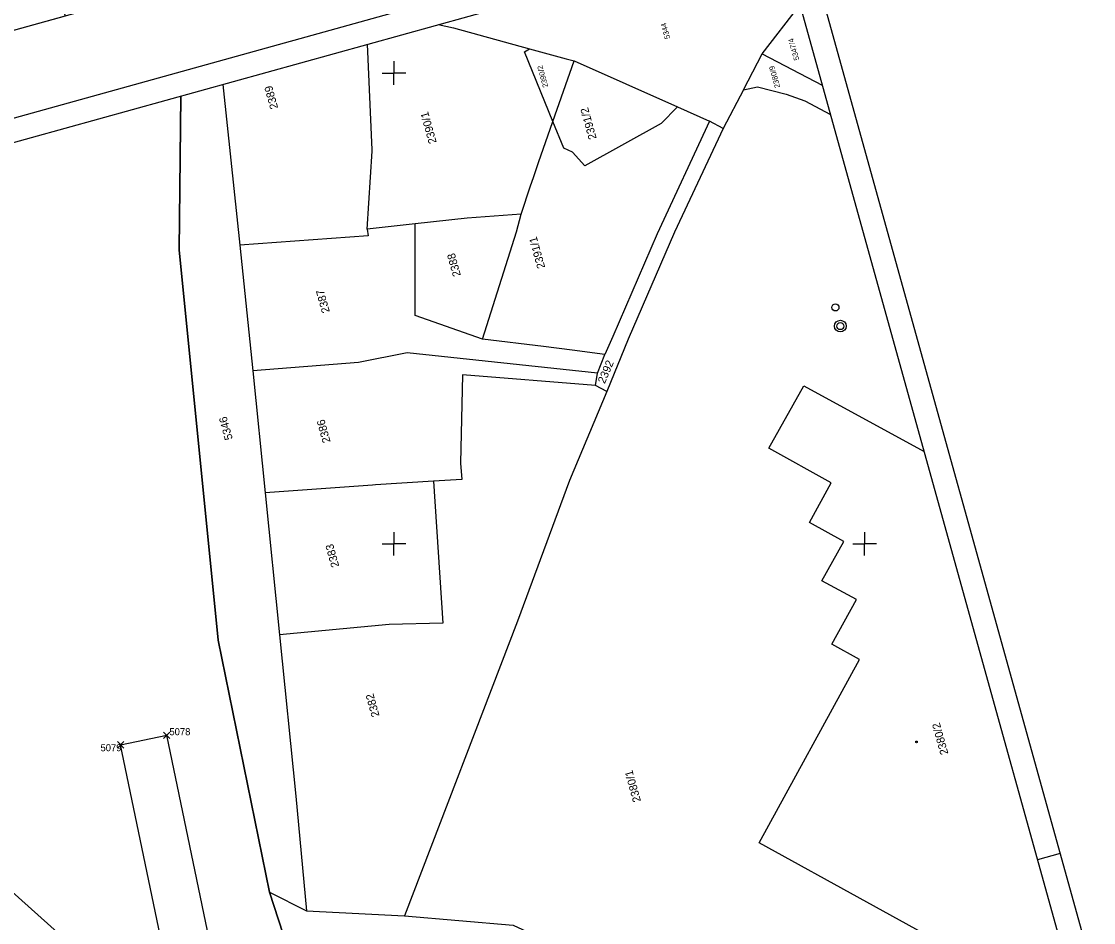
# Model space of a CAD drawing. Extents: x -821172 to -820632, y -1070921 to -1069931.
# Drawn here: x -820939.6 to -820825.7, y -1070140.2 to -1070044.5 of the extents above; entities that cross this region are included whole.
import ezdxf

# ---------------------------------------------------------------- set-up
doc = ezdxf.new("R2010")
doc.units = 0
for name, color, linetype in [('Popisove_pole', 7, 'Continuous'), ('Ram', 7, 'Continuous'), ('Sit', 7, 'Continuous'), ('VB_bod_DZ', 7, 'Continuous'), ('Vrstva 52', 7, 'Continuous'), ('Vrstva 53', 7, 'Continuous'), ('Vrstva 55', 7, 'Continuous'), ('Vrstva 57', 7, 'Continuous'), ('Vrstva 59', 7, 'Continuous'), ('Vrstva 7', 7, 'Continuous')]:
    doc.layers.add(name, color=color, linetype=linetype)

msp = doc.modelspace()

# ---------------------------------------------------------------- linework, layer by layer
at = {"layer": 'Popisove_pole'}
for points in [[(-820992.73, -1070060.01), (-821015.48, -1069978.12), (-820890.23, -1069943.31), (-820867.47, -1070025.21)], [(-820946.96, -1070047.3), (-820969.72, -1069965.4), (-820957.67, -1069962.05), (-820934.92, -1070043.95)]]:
    msp.add_lwpolyline(points, close=True, dxfattribs=at)
at = {"layer": 'Ram'}
for p, q in [((-820859.09, -1070034.8), (-821140.43, -1070112.97)), ((-820829.24, -1070132.89), (-820831.65, -1070133.56))]:
    msp.add_line(p, q, dxfattribs=at)
for points in [[(-820857.35, -1070031.72), (-821000.43, -1070071.48)], [(-820857.35, -1070031.72), (-820632.46, -1070841.06)], [(-820859.09, -1070034.8), (-820635.54, -1070839.32), (-820916.88, -1070917.49)]]:
    msp.add_lwpolyline(points, dxfattribs=at)
at = {"layer": 'Sit'}
for p, q in [((-820900, -1070048.75), (-820900, -1070050)), ((-820901.25, -1070050), (-820900, -1070050)), ((-820898.75, -1070050), (-820900, -1070050)), ((-820900, -1070051.25), (-820900, -1070050)), ((-820900, -1070098.75), (-820900, -1070100)), ((-820850, -1070098.75), (-820850, -1070100)), ((-820901.25, -1070100), (-820900, -1070100)), ((-820898.75, -1070100), (-820900, -1070100)), ((-820900, -1070101.25), (-820900, -1070100)), ((-820851.25, -1070100), (-820850, -1070100)), ((-820848.75, -1070100), (-820850, -1070100)), ((-820850, -1070101.25), (-820850, -1070100))]:
    msp.add_line(p, q, dxfattribs=at)
at = {"layer": 'VB_bod_DZ'}
for p, q in [((-820924.48, -1070120.68), (-820923.79, -1070119.99)), ((-820923.79, -1070120.68), (-820924.48, -1070119.99)), ((-820929.37, -1070121.7), (-820928.68, -1070121.01)), ((-820928.68, -1070121.7), (-820929.37, -1070121.01))]:
    msp.add_line(p, q, dxfattribs=at)
at = {"layer": 'Vrstva 52'}
msp.add_line((-820929.03, -1070121.35), (-820924.13, -1070120.33), dxfattribs=at)
for points in [[(-820888.38, -1070203.11), (-820893.8, -1070195), (-820900.76, -1070183.17), (-820906.67, -1070169.8), (-820914.74, -1070165.47), (-820924.13, -1070120.33)], [(-820905.06, -1070185.73), (-820910.61, -1070187.13), (-820917.29, -1070174.93), (-820923.8, -1070161.07), (-820931.72, -1070145.81), (-820933.72, -1070143.08), (-820957.69, -1070121.63)], [(-820905.06, -1070185.73), (-820905.22, -1070185.45), (-820910.55, -1070173.4), (-820919.16, -1070168.77), (-820929.03, -1070121.35)]]:
    msp.add_lwpolyline(points, dxfattribs=at)
at = {"layer": 'Vrstva 53'}
for points in [[(-820922.62, -1070052.45), (-820922.83, -1070068.79), (-820918.68, -1070110.25), (-820913.23, -1070137.01)], [(-820913.23, -1070137.01), (-820910.8, -1070144.4), (-820907.37, -1070147.11)]]:
    msp.add_lwpolyline(points, dxfattribs=at)
at = {"layer": 'Vrstva 55'}
for p, q in [((-820860.9, -1070047.95), (-820856.87, -1070042.78)), ((-820862.88, -1070051.77), (-820860.9, -1070047.95)), ((-820860.9, -1070047.95), (-820854.51, -1070051.28)), ((-820883.11, -1070055.15), (-820880.86, -1070048.72)), ((-820880.86, -1070048.72), (-820869.88, -1070053.59)), ((-820862.88, -1070051.77), (-820865.03, -1070055.9)), ((-820869.88, -1070053.59), (-820866.48, -1070055.1)), ((-820865.03, -1070055.9), (-820866.48, -1070055.1)), ((-820897.74, -1070066.03), (-820902.85, -1070066.6)), ((-820916.36, -1070068.27), (-820914.97, -1070081.64)), ((-820878.36, -1070081.89), (-820877.58, -1070079.88)), ((-820914.97, -1070081.64), (-820913.68, -1070094.59)), ((-820878.59, -1070083.2), (-820878.36, -1070081.89)), ((-820877.39, -1070083.81), (-820878.59, -1070083.2)), ((-820913.68, -1070094.59), (-820912.16, -1070109.68)), ((-820913.23, -1070137.01), (-820909.27, -1070138.99)), ((-820909.27, -1070138.99), (-820898.88, -1070139.5))]:
    msp.add_line(p, q, dxfattribs=at)
for points in [[(-820895.31, -1070044.86), (-820893.67, -1070045.22), (-820885.61, -1070047.42)], [(-820902.85, -1070066.6), (-820902.3, -1070058.3), (-820902.3, -1070058.17), (-820902.8, -1070046.94)], [(-820883.11, -1070055.15), (-820886.13, -1070047.76), (-820885.61, -1070047.42)], [(-820885.61, -1070047.42), (-820881.69, -1070048.49), (-820880.86, -1070048.72)], [(-820918.18, -1070051.22), (-820917.32, -1070059.26), (-820916.36, -1070068.27)], [(-820913.23, -1070137.01), (-820918.68, -1070110.25), (-820922.83, -1070068.79), (-820922.62, -1070052.43)], [(-820862.88, -1070051.77), (-820861.37, -1070051.48), (-820858.35, -1070052.26), (-820856.35, -1070052.96), (-820853.61, -1070054.39)], [(-820869.88, -1070053.59), (-820871.63, -1070055.37), (-820879.71, -1070059.86), (-820881.02, -1070058.42), (-820881.94, -1070057.97), (-820883.11, -1070055.15)], [(-820886.5, -1070064.99), (-820885.48, -1070061.97), (-820885.19, -1070061.1), (-820884.63, -1070059.51), (-820883.11, -1070055.15)], [(-820866.48, -1070055.1), (-820872.03, -1070067.08), (-820876.75, -1070077.98), (-820877.58, -1070079.88)], [(-820865.03, -1070055.9), (-820870.19, -1070066.92), (-820875.13, -1070078.28), (-820877.39, -1070083.81)], [(-820886.5, -1070064.99), (-820892.22, -1070065.41), (-820897.74, -1070066.03)], [(-820890.6, -1070078.28), (-820886.98, -1070066.87), (-820886.5, -1070064.99)], [(-820890.6, -1070078.28), (-820897.74, -1070075.76), (-820897.74, -1070066.03)], [(-820902.85, -1070066.6), (-820902.73, -1070067.28), (-820916.36, -1070068.27)], [(-820877.58, -1070079.88), (-820881.08, -1070079.43), (-820884.11, -1070079.05), (-820890.6, -1070078.28)], [(-820878.36, -1070081.89), (-820898.58, -1070079.72), (-820903.75, -1070080.75), (-820914.97, -1070081.64)], [(-820878.59, -1070083.2), (-820892.71, -1070082.07), (-820892.93, -1070091.44), (-820892.8, -1070093.17), (-820895.78, -1070093.35)], [(-820826.9, -1070150.65), (-820861.21, -1070131.75), (-820850.55, -1070112.3), (-820853.49, -1070110.66), (-820850.87, -1070105.91), (-820854.53, -1070103.94), (-820852.21, -1070099.75), (-820855.86, -1070097.75), (-820853.56, -1070093.52), (-820860.16, -1070089.86), (-820856.47, -1070083.21), (-820843.69, -1070090.21)], [(-820877.39, -1070083.81), (-820881.36, -1070093.26), (-820886.87, -1070108.2), (-820898.88, -1070139.5)], [(-820895.78, -1070093.35), (-820901.94, -1070093.75), (-820902.26, -1070093.79), (-820913.68, -1070094.59)], [(-820895.78, -1070093.35), (-820894.81, -1070108.42), (-820900.5, -1070108.58), (-820912.16, -1070109.68)], [(-820912.16, -1070109.68), (-820910.42, -1070126.82), (-820909.27, -1070138.99)], [(-820907.37, -1070147.11), (-820910.8, -1070144.4), (-820913.23, -1070137.01)], [(-820898.88, -1070139.5), (-820887.34, -1070140.5), (-820850.84, -1070157.46)]]:
    msp.add_lwpolyline(points, dxfattribs=at)
at = {"layer": 'Vrstva 59'}
msp.add_circle((-820844.49, -1070121.04), 0.0875, dxfattribs=at)
at = {"layer": 'Vrstva 7'}
for centre, radius in [((-820853.1, -1070074.9), 0.375), ((-820853.1, -1070074.9), 0.375), ((-820852.58, -1070076.88), 0.623), ((-820852.58, -1070076.88), 0.623), ((-820852.58, -1070076.88), 0.376), ((-820852.58, -1070076.88), 0.376)]:
    msp.add_circle(centre, radius, dxfattribs=at)

# ---------------------------------------------------------------- texts
at = {"layer": 'VB_bod_DZ'}
for s, p in [(' 5078', (-820924.13, -1070120.33)), (' 5079', (-820931.45, -1070122.03))]:
    msp.add_text(s, height=0.75, dxfattribs=at).set_placement(p)
at = {"layer": 'Vrstva 57'}
for s, height, rotation, p in [('5344', 0.569, 105.5289, (-820870.65, -1070046.31)), ('5347/4', 0.569, 105.5289, (-820856.93, -1070048.58)), ('2390/2', 0.569, 105.5289, (-820883.6, -1070051.46)), ('2380/9', 0.569, 105.5289, (-820858.97, -1070051.5)), ('2389', 0.85, 105.5289, (-820912.29, -1070053.71)), ('2391/2', 0.85, 105.5289, (-820878.46, -1070056.94)), ('2390/1', 0.85, 105.5289, (-820895.45, -1070057.38)), ('2391/1', 0.85, 105.5289, (-820883.92, -1070070.65)), ('2388', 0.85, 105.5289, (-820892.88, -1070071.5)), ('2387', 0.85, 105.5289, (-820906.8, -1070075.36)), ('2392', 0.85, 66.8729, (-820877.61, -1070083.06)), ('5346', 0.85, 105.5289, (-820917.11, -1070088.85)), ('2386', 0.85, 105.5289, (-820906.72, -1070089.16)), ('2383', 0.85, 105.5289, (-820905.8, -1070102.38)), ('2382', 0.85, 105.5289, (-820901.52, -1070118.27)), ('2380/2', 0.85, 105.5289, (-820841.1, -1070122.28)), ('2380/1', 0.85, 105.5289, (-820873.75, -1070127.32))]:
    msp.add_text(s, height=height, rotation=rotation, dxfattribs=at).set_placement(p)

doc.saveas('drawing.dxf')
